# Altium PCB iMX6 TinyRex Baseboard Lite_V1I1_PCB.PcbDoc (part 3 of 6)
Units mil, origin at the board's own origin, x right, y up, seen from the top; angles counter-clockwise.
Board outline 3149.61 x 3543.31 mil, 6 copper layers (L1, L2, L3, L4 (PWR), L5, L6), stack 60.634 mil thick; 385 components, 309 nets, 1566 pads, 914 vias.
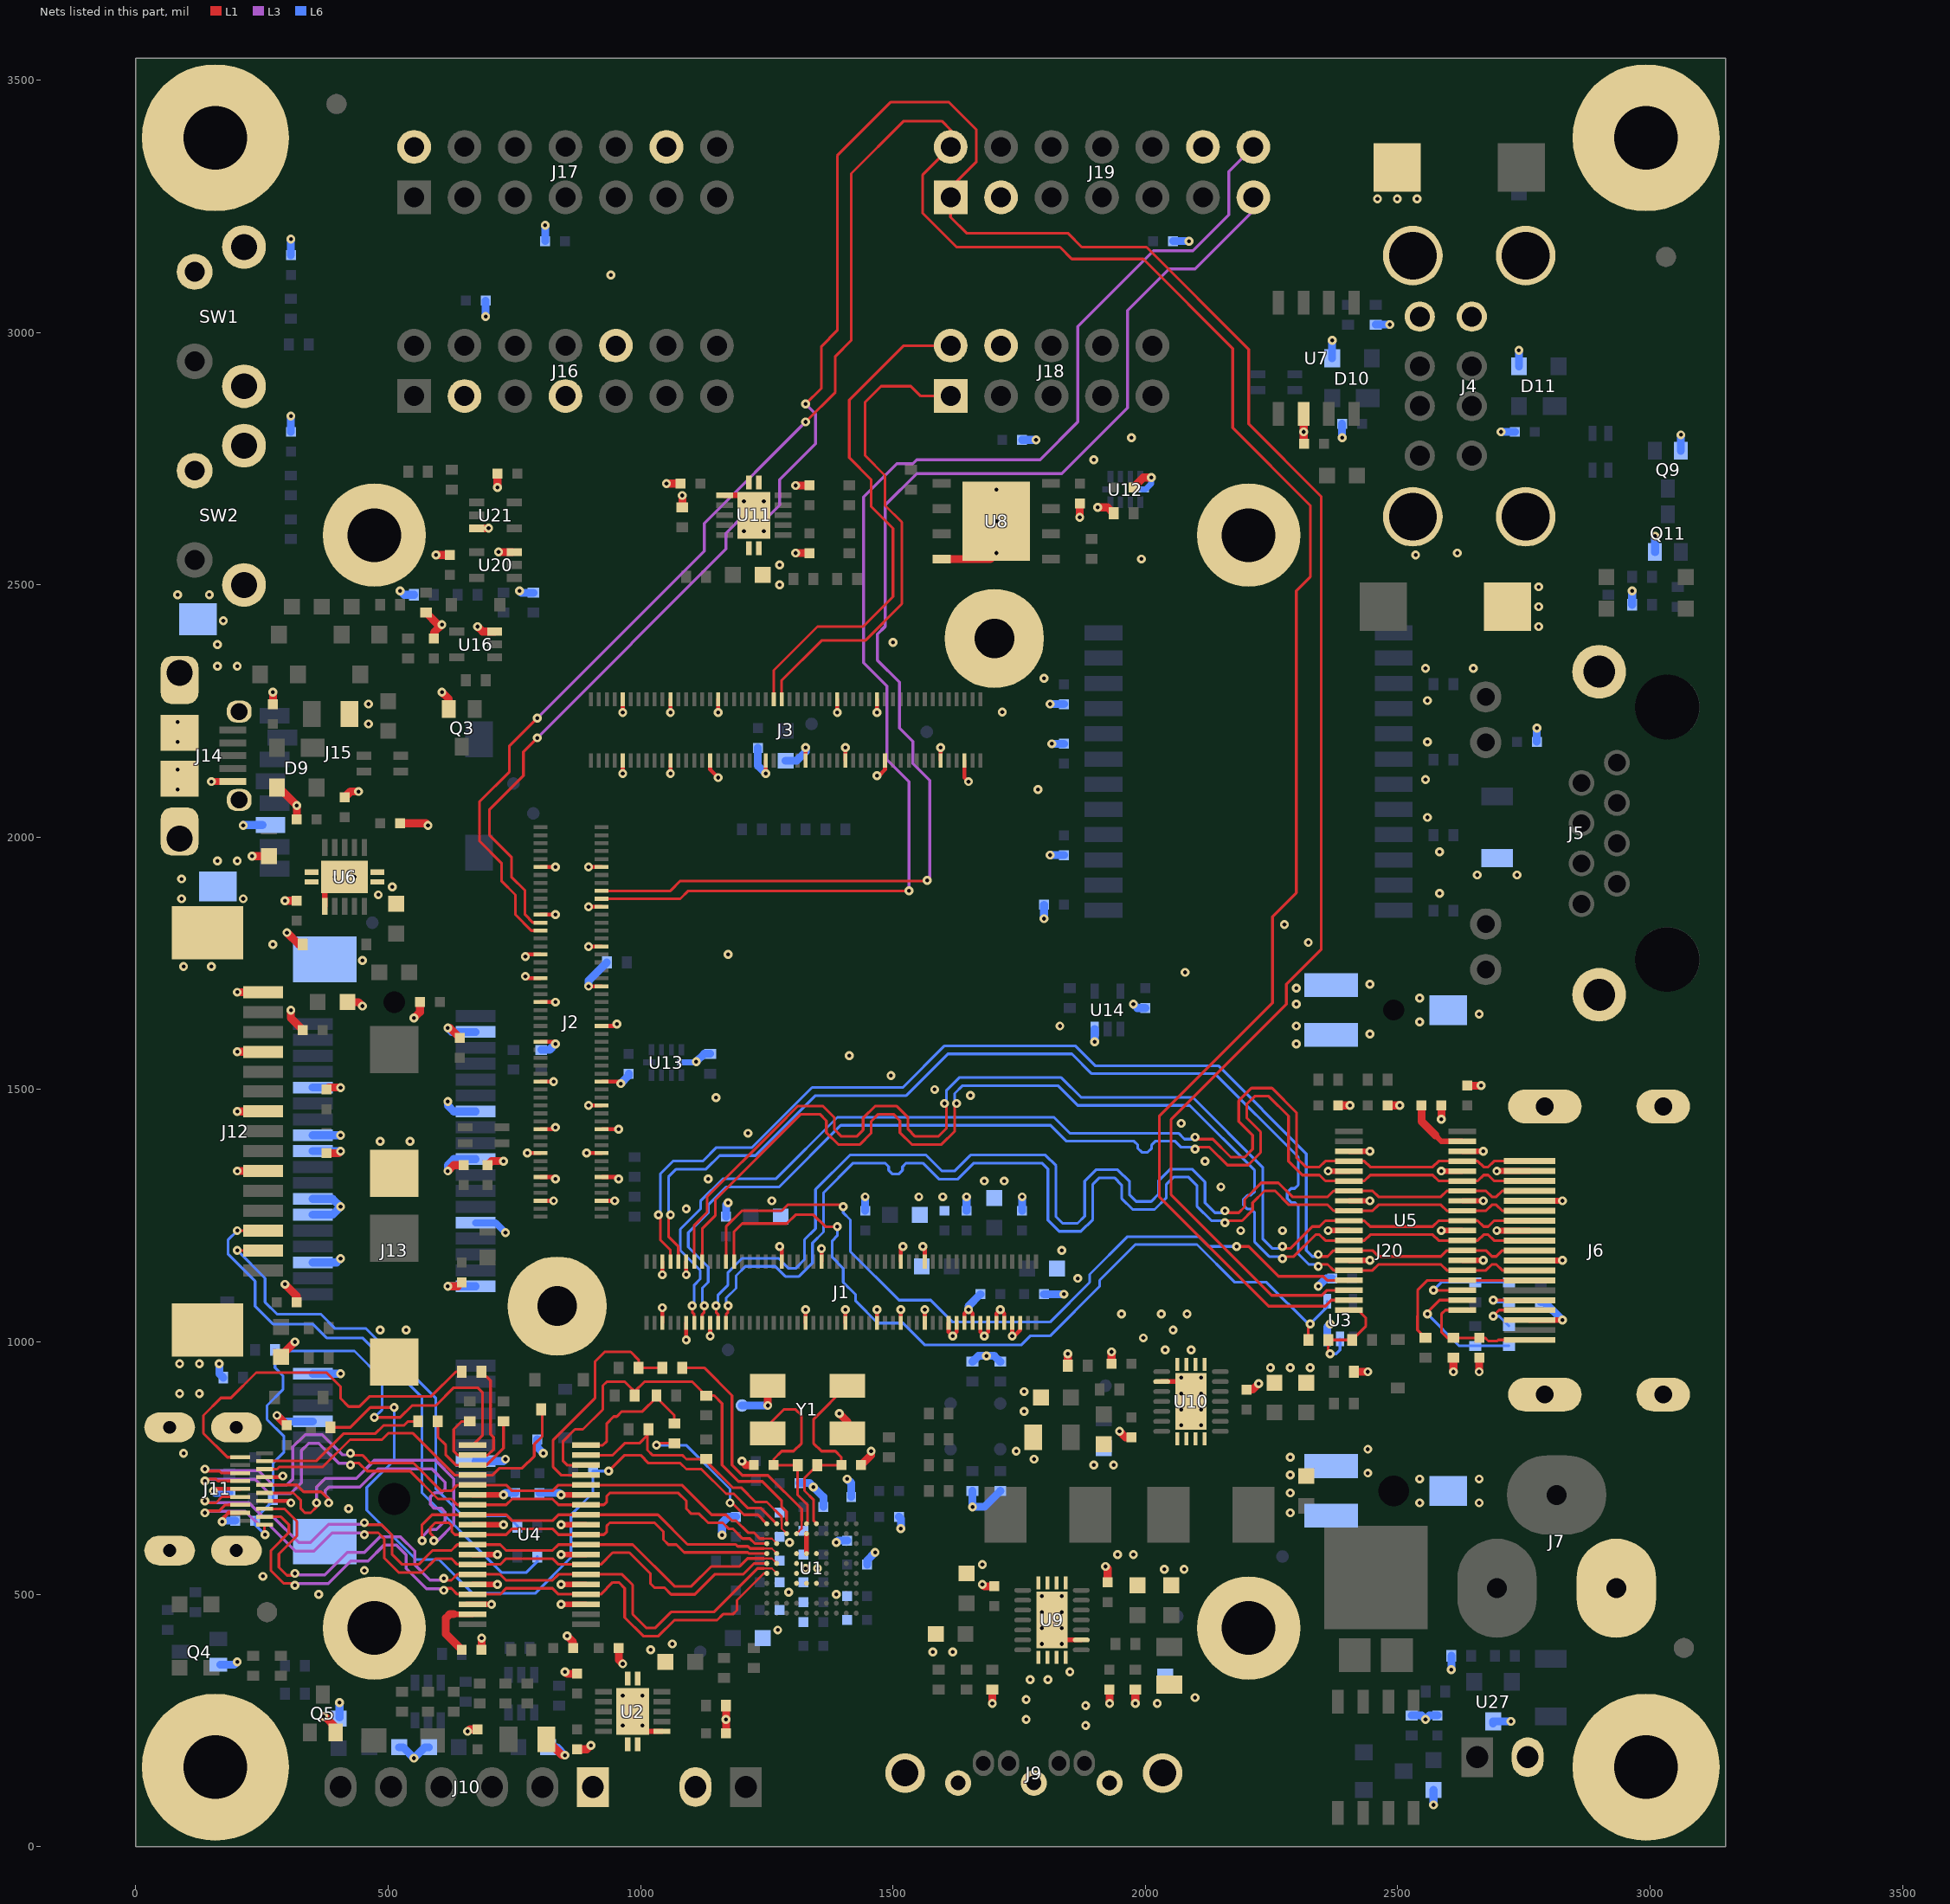
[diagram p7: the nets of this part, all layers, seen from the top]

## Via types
v1: diameter 17.72, hole 7.87, L1 to L6, 471 vias
v2: diameter 17.72, hole 7.87, L1 to L6, tented both sides, 442 vias
v3: diameter 17.72, hole 7.87, L1 to L6, tented top, 1 vias

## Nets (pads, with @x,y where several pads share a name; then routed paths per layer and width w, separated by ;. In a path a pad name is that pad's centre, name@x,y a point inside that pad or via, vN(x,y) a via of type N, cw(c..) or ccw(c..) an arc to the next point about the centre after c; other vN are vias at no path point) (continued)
GND: C1.2 C2.2 C3.2 C4.2 C5.2 C6.2 C7.2 C8.2 C9.1 C10.2 C11.2 C12.2 C13.2 C14.2 C15.2 C16.2 C17.2 C18.2 C19.2 C20.2 C21.2 C22.2 C23.2 C24.2 C25.2 C26.2 C27.1 C28.1 C29.2 C30.2 C31.2 C32.2 C33.2 C34.2 C35.2 C36.2 C37.2 C38.2 C39.2 C40.2 C41.1 C42.1 C43.1 C44.1 C45.2 C46.2 C47.2 C48.2 C49.2 C50.2 C51.2 C52.1 C53.1 C54.1 C55.1 C56.2 C57.2 C58.2 C59.2 C60.2 C61.2 C62.2 C63.2 C64.2 C65.2 C66.2 C67.2 C68.2 C69.2 C70.2 C71.2 C72.2 C73.2 C74.2 C75.1 C76.1 C77.2 C78.2 C79.2 C89.2 C90.2 C91.2 C92.2 C106.2 C108.2 C114.1 C115.2 C116.1 C117.1 C118.1 C119.2 C156.2 C158.2 C159.2 C160.2 C161.2 C165.2 C171.2 C176.2 C177.1 C183.2 C184.2 C185.2 C187.1 C188.1 C190.1 C198.2 C200.2 C203.2 C230.1 C231.2 C232.2 C257.2 C258.2 C259.2 C260.2 C261.2 C262.2 C263.2 C264.2 C265.2 C266.2 C267.2 C268.2 C381.2 D4.2 D8.2 D9.3 D10.3 D11.3 D12.2 D13.2 D19.2 J1.5 J1.7 J1.9 J1.11 J1.13 J1.15 J1.17 J1.19 J1.21 J1.23 J1.29 J1.30 J1.35 J1.36 J1.41 J1.49 J1.56 J1.59 J1.66 J1.83 J1.89 J1.90 J1.95 J1.96 J2.11 J2.12 J2.21 J2.24 J2.31 J2.34 J2.40 J2.41 J2.46 J2.51 J2.56 J2.65 J2.66 J2.71 J2.77 J2.78 J2.83 J2.84 J2.89 J2.90 J2.95 J2.96 J3.5 J3.11 J3.25 J3.28 J3.35 J3.38 J3.45 J3.55 J3.68 J3.69 J3.79 J3.80 J3.91 J3.92 J4.4 J4.8 J4.9 J4.10 J4.11 J4.12 J5.13 J5.14 J6.2 J6.5 J6.8 J6.11 J6.17 J6.MTG1 J6.MTG2 J6.MTG3 J6.MTG4 J7.2 J8.2 J9.1 J9.4 J9.7 J9.8 J9.9 J10.1 J11.4 J11.7 J11.10 J11.13 J11.MTG1 J11.MTG2 J11.MTG3 J11.MTG4 J12.1 J12.4 J12.7 J12.10 J12.16 J12.17 J13.4 J13.9 J13.15 J13.18 J13.21 J13.26 J13.27 J13.29 J13.34 J13.35 J13.37 J13.40 J13.43 J13.50 J13.53 J13.54 J14.5 J14.6 J14.7 J14.8 J14.9 J14.10 J14.11 J15.6 J15.11 J15.12 J16.3 J16.7 J16.10 J17.2 J17.12 J18.4 J19.3 J19.12 J20.1 J20.2 J20.3 J20.4 J20.5 J20.6 JP1.2 MH1.1 MH2.1 MH3.1 MH4.1 MH5.1 MH6.1 MH9.1 MH10.1 MH11.1 MH12.1 Q3.2 Q4.2 Q5.2 Q9.2 Q11.2 R1.1 R2.1 R3.1 R4.1 R14.2 R20.1 R23.1 R25.1 R29.1 R38.1 R44.1 R45.1 R47.1 R52.1 R53.1 R64.1 R67.1 R83.1 R139.1 R162.2 R213.1 R217.1 R226.1 R247.1 R296.1 R301.1 SW1.1 SW1.3 SW1.4 SW2.1 SW2.3 SW2.4 TP10.1 U1.B5 U1.D4 U1.D5 U1.D6 U1.E4 U1.F4 U1.G4 U1.G5 U1.G6 U2.6 U2.11 U2.12 U2.13 U2.14 U2.15 U3.3 U4.3 U4.5 U4.8 U4.11 U4.14 U4.25 U4.28 U4.31 U4.34 U4.36 U5.3 U5.5 U5.8 U5.11 U5.14 U5.25 U5.28 U5.31 U5.34 U5.36 U6.6 U6.11 U6.12 U6.13 U6.14 U6.15 U7.6 U8.4 U8.9 U9.2 U9.15 U9.16 U9.17 U9.18 U9.19 U9.20 U9.21 U9.22 U9.23 U10.2 U10.15 U10.16 U10.17 U10.18 U10.19 U10.20 U10.21 U10.22 U10.23 U11.6 U11.11 U11.12 U11.13 U11.14 U11.15 U12.5 U13.5 U14.3 U16.3 U20.3 U21.3 U27.3 Y1.2 Y1.4 | length 9107.6
  L1 w7.87: v1(153.54,704.72) 157.48,708.66 J11.10@206.69,708.66 ; v1(171.26,643.7) 171.26,649.2 183.47,661.42 J11.4@206.69,661.42 ; J11.7@254.92,685.04 303.15,685.04 v1(307.09,681.1) ; J11.13@254.92,732.28 289.37,732.28 v1(291.34,734.25) ; v2(771.65,1724.41) 775.59,1720.47 J2.40@801.57,1720.47 ; v2(771.65,1763.78) 775.59,1767.72 J2.34@801.57,1767.72 ; v2(775.59,1374.02) J2.84@801.57,1374.02 ; J2.96@801.57,1279.53 v2(827.56,1279.53) ; J2.90@801.57,1326.77 827.56,1326.77 v2(831.5,1322.84) ; J2.78@801.57,1421.26 827.56,1421.26 v2(831.5,1425.2) ; J2.66@801.57,1515.75 v2(827.56,1515.75) ; J2.56@801.57,1594.49 827.56,1594.49 v2(831.5,1590.55) ; J2.46@801.57,1673.23 v2(831.5,1673.23) ; J2.24@801.57,1846.46 v2(831.5,1846.46) ; J2.12@801.57,1940.94 v2(831.5,1940.94) ; v2(892.91,1374.02) J2.83@922.83,1374.02 ; v2(896.85,1468.5) J2.71@922.83,1468.5 ; v2(896.85,1704.72) J2.41@922.83,1704.72 ; v2(896.85,1783.46) J2.31@922.83,1783.46 ; v2(896.85,1862.2) J2.21@922.83,1862.2 ; v2(896.85,1940.94) J2.11@922.83,1940.94 ; J2.95@922.83,1279.53 v2(948.82,1279.53) ; J2.89@922.83,1326.77 952.76,1326.77 v2(956.69,1322.84) ; J2.77@922.83,1421.26 v2(956.69,1421.26) ; J2.65@922.83,1515.75 956.69,1515.75 v2(960.63,1511.81) ; J2.51@922.83,1625.98 948.82,1625.98 v2(952.76,1629.92) ; v2(964.57,2125.98) J3.91@964.57,2151.97 ; v2(964.57,2247.24) J3.92@964.57,2273.23 ; J1.95@1043.31,1037.8 v2(1043.31,1067.72) ; v2(1043.31,1133.07) J1.96@1043.31,1159.06 ; v2(1059.06,2125.98) J3.79@1059.06,2151.97 ; v2(1059.06,2247.24) J3.80@1059.06,2273.23 ; v2(1090.55,1003.94) J1.89@1090.55,1037.8 ; v2(1090.55,1133.07) J1.90@1090.55,1159.06 ; v2(1137.8,1011.81) J1.83@1137.8,1037.8 ; J3.69@1137.8,2151.97 1137.8,2133.86 v2(1153.54,2118.11) ; v2(1153.54,2247.24) J3.68@1153.54,2273.23 ; v2(1248.03,2125.98) J3.55@1248.03,2151.97 ; v2(1275.59,1188.98) 1279.53,1185.04 J1.66@1279.53,1159.06 ; J1.59@1326.77,1037.8 v2(1326.77,1063.78) ; J3.45@1326.77,2151.97 v2(1326.77,2177.95) ; J1.56@1358.27,1159.06 v2(1358.27,1185.04) ; v2(1389.76,2247.24) J3.38@1389.76,2273.23 ; J1.49@1405.51,1037.8 v2(1405.51,1063.78) ; J3.35@1405.51,2151.97 v2(1405.51,2177.95) ; J1.41@1468.5,1037.8 v2(1468.5,1063.78) ; v2(1468.5,2122.05) 1472.44,2122.05 1484.25,2133.86 J3.25@1484.25,2151.97 ; v2(1468.5,2247.24) J3.28@1468.5,2273.23 ; J1.35@1515.75,1037.8 v2(1515.75,1063.78) ; J1.36@1515.75,1159.06 v2@1515.75,1185.04 ; v2(1559.06,1188.98) 1562.99,1185.04 J1.30@1562.99,1159.06 ; J1.29@1562.99,1037.8 v2(1562.99,1063.78) ; J3.11@1594.49,2151.97 v2(1594.49,2177.95) ; J1.23@1610.24,1037.8 1610.24,1019.69 v2(1618.11,1011.81) 1625.98,1019.68 J1.21@1625.98,1037.8 ; J1.19@1641.73,1037.8 1641.73,1055.91 v2(1649.61,1063.78) 1657.48,1055.91 J1.17@1657.48,1037.8 ; J3.5@1641.73,2151.97 1641.73,2118.11 v2(1649.61,2110.24) ; J1.15@1673.23,1037.8 1673.23,1019.69 v2(1681.1,1011.81) 1688.98,1019.68 J1.13@1688.98,1037.8 ; J1.11@1704.72,1037.8 1704.72,1055.91 v2(1712.6,1063.78) 1720.47,1055.91 J1.9@1720.47,1037.8 ; J1.7@1736.22,1037.8 v2(1736.22,1011.81) 1740.16,1011.81 1751.97,1023.62 J1.5@1751.97,1037.8
  L1 w9.45: v1(1834.65,401.57) 1842.52,409.45 U9.2@1873.03,409.45 ; U10.2@2031.5,921.26 U10.15@2070.87,921.26
  L1 w9.84: U1.D5@1328.74,580.71 U1.B5@1328.74,620.08
  L1 w11.02: U6.6@374.02,1863.19 U6.11@374.02,1891.93 ; U4.36@655.51,480.32 v1(704.72,480.32) ; U4.34@667.32,519.69 v1(716.54,519.69) ; U4.31@667.32,578.74 v1(716.54,578.74) ; U4.28@667.32,637.8 v1(728.35,637.8) ; U4.25@667.32,696.85 v1(728.35,696.85) ; v1(842.52,480.32) U4.3@891.73,480.32 ; v1(842.52,519.69) U4.5@891.73,519.69 ; v1(842.52,578.74) U4.8@891.73,578.74 ; v1(842.52,637.8) U4.11@891.73,637.8 ; v1(842.52,696.85) U4.14@891.73,696.85 ; U2.11@1013.58,228.35 U2.6@1042.32,228.35 ; U11.6@1166.34,2677.17 U11.11@1195.08,2677.17 ; v2(2362.21,1220.47) U5.11@2403.54,1220.47 ; v2(2362.21,1338.58) U5.5@2403.54,1338.58 ; U5.14@2403.54,1161.42 v2(2444.88,1161.42) ; U5.8@2403.54,1279.53 v2(2444.88,1279.53) ; U5.3@2403.54,1377.95 v2(2444.88,1377.95) ; v2(2586.61,1220.47) U5.28@2627.95,1220.47 ; v2(2586.61,1338.58) U5.34@2627.95,1338.58 ; U5.25@2627.95,1161.42 v2(2669.29,1161.42) ; U5.31@2627.95,1279.53 v2(2669.29,1279.53) ; U5.36@2627.95,1377.95 v2(2669.29,1377.95)
  L1 w11.81: v2(2696.46,1220.47) J6.8@2761.42,1220.47 ; v2(2696.46,1338.58) J6.2@2761.42,1338.58 ; J6.17@2761.42,1043.31 v2(2826.38,1043.31) ; J6.11@2761.42,1161.42 v2(2826.38,1161.42) ; J6.5@2761.42,1279.53 v2(2826.38,1279.53)
  L1 w13.78: v1(149.61,2110.24) J14.5@191.93,2110.24
  L1 w15.75: v1(200.79,1338.58) J12.10@251.97,1338.58 ; v1(200.79,1456.69) J12.7@251.97,1456.69 ; v1(200.79,1574.8) J12.4@251.97,1574.8 ; v1(200.79,1692.91) J12.1@251.97,1692.91 ; v1(230.31,1962.6) D19.2@263.78,1962.6 ; C26.2@271.65,2263.78 v1(271.65,2287.4) ; v1(279.53,854.33) C74.2@299.21,834.65 ; C31.2@279.53,974.41 289.37,974.41 v1(314.96,1000) ; D9.3@279.53,2098.43 283.46,2098.43 v1(318.9,2062.99) C158.2@318.9,2035.43 ; v1(295.28,1114.17) 318.9,1090.55 C32.2@318.9,1078.74 ; v1(295.28,1874.02) C21.2@318.9,1874.02 ; v1(299.21,1811.02) 322.83,1787.4 R20.1@330.71,1787.4 ; v1(307.09,1657.48) 307.09,1641.73 C69.2@330.71,1618.11 ; v1(372.05,257.87) 374.02,257.87 395.67,236.22 Q5.2@395.67,226.38 ; C263.2@377.95,1374.02 401.57,1374.02 v1(405.51,1377.95) ; C268.2@377.95,1500 381.89,1503.94 v1(405.51,1503.94) ; C19.2@413.39,2078.74 425.2,2090.55 v1(440.94,2090.55) ; C60.2@419.29,1673.23 440.95,1673.23 v1(448.82,1665.35) ; C18.2@523.62,2027.56 574.8,2027.56 v1(578.74,2023.62) ; v1(551.18,1641.73) 562.99,1653.54 C267.2@562.99,1673.23 ; R45.1@574.8,2444.88 598.43,2421.26 v1(606.3,2421.26) 590.55,2405.51 C230.1@590.55,2393.7 ; v1(594.49,2559.06) C171.2@622.05,2559.06 ; v1(606.3,2287.4) 620.08,2273.62 Q3.2@620.08,2253.94 ; v1(618.11,1110.24) 637.8,1110.24 C266.2@645.67,1118.11 ; v1(618.11,1338.58) 629.92,1350.39 C260.2@649.61,1350.39 ; v1(618.11,1622.05) 622.05,1622.05 C261.2@641.73,1602.36 ; v1(657.48,228.35) 661.42,232.28 C77.2@673.23,232.28 ; U21.3@671.26,2612.2 v1(698.82,2612.2) ; v1(677.17,2417.32) 687.01,2407.48 U16.3@710.63,2407.48 ; C73.2@685.04,389.76 v1(685.04,413.39) ; C262.2@696.85,1350.39 704.72,1358.27 v1(728.35,1358.27) ; v1(716.54,2692.91) C176.2@716.54,2720.47 ; v1(718.5,2564.96) U20.3@746.06,2564.96 ; C78.2@812.99,212.6 844.49,181.1 v1(850.39,181.1) ; v1(850.39,346.46) 854.33,342.52 C56.2@874.02,342.52 ; v1(854.33,417.32) 866.14,405.51 C72.2@866.14,393.7 ; C57.2@874.02,192.91 893.7,192.91 v1(901.57,200.79) ; C71.2@956.69,393.7 956.69,370.08 v1(964.57,362.2) ; v2(1051.18,2700.79) C92.2@1078.74,2700.79 ; R226.1@1082.68,2653.54 v2(1082.68,2677.17) ; C59.2@1169.29,224.41 v1(1169.29,251.97) R83.1@1169.29,279.53 ; v1(1200.79,763.78) 1208.66,755.91 C48.2@1224.41,755.91 ; v1(1251.97,874.02) Y1.4@1251.97,913.39 ; v2(1307.09,2562.99) C89.2@1334.65,2562.99 ; v2(1307.09,2696.85) C90.2@1334.65,2696.85 ; v1(1393.7,858.27) 1409.45,842.52 Y1.2@1409.45,818.9 ; C49.2@1437.01,755.91 1456.69,775.59 v1(1456.69,783.46) ; U8.4@1596.46,2550.98 1692.72,2550.98 v1(1704.72,2562.99) ; v1(1677.17,519.69) 1681.1,515.75 C39.2@1700.79,515.75 ; v1(1696.85,283.46) R25.1@1696.85,311.02 ; R217.1@1846.46,952.76 v2(1846.46,976.38) ; v1(1870.08,2633.86) C203.2@1870.08,2661.42 ; v2(1905.51,2653.54) 1925.2,2653.54 R23.1@1937.01,2641.73 ; v1(1921.26,555.12) 1925.2,551.18 C40.2@1925.2,523.62 ; v1(1929.13,283.46) C64.2@1929.13,311.02 ; C33.2@1933.07,956.69 v2(1933.07,980.31) ; v2(1948.82,822.83) 1960.63,811.02 C68.2@1972.44,811.02 ; C9.1@1976.38,2692.91 1996.06,2712.6 v2(2011.81,2712.6) ; v1(1980.32,283.46) R213.1@1980.32,311.02 ; C67.2@2200.79,905.51 2212.6,905.51 v2(2224.41,917.32) ; C165.2@2313.58,2779.53 U7.6@2313.58,2838.58 ; C23.2@2381.89,1468.5 v2(2405.51,1468.5) ; R29.1@2413.39,940.94 v2(2440.94,940.94) ; C22.2@2480.31,1468.5 v2(2503.94,1468.5) ; v2(2586.61,1440.94) C24.2@2586.61,1468.5 ; v2(2610.24,940.94) R47.1@2610.24,968.5 ; C25.2@2637.8,1507.87 v2(2665.35,1507.87) ; v2(2661.42,940.94) C108.2@2661.42,968.5
  L6 w11.81: U13.5@1085.04,1553.67 1108.79,1553.67 v2(1110.24,1555.12) ; U12.5@1994.49,2688.98 2000.39,2688.98 2011.81,2700.4 v2(2011.81,2712.6)
  L6 w13.78: J13.26@673.23,1236.22 712.6,1236.22 v1(732.28,1216.54)
  L6 w15.75: v1(153.54,704.72) 157.48,700.79 R162.2@185.04,700.79 ; v1(165.35,956.69) 165.35,937.01 R38.1@173.23,929.13 ; Q4.2@167.32,360.24 194.88,360.24 v1(200.79,366.14) ; v1(171.26,643.7) 173.23,645.67 C8.2@196.85,645.67 ; v2@212.6,2024.21 J15.6@250.98,2024.21 ; v1(279.53,854.33) 291.34,842.52 J13.9@350.39,842.52 ; C200.2@307.09,2803.15 v1(307.09,2834.65) ; C198.2@307.09,3153.54 v1(307.09,3185.04) ; J13.15@350.39,937.01 v1(405.51,937.01) ; J13.21@350.39,1157.48 397.64,1157.48 v1(405.51,1165.35) ; J13.27@350.39,1251.97 389.76,1251.97 v1(405.51,1267.72) 389.76,1283.47 J13.29@350.39,1283.47 ; J13.35@350.39,1377.95 v1(405.51,1377.95) ; J13.37@350.39,1409.45 v1(405.51,1409.45) ; J13.43@350.39,1503.94 v1(405.51,1503.94) ; D12.2@403.54,255.91 v1(403.54,285.43) ; D8.2@521.65,196.85 529.53,196.85 v1(551.18,175.2) 572.83,196.85 D4.2@580.71,196.85 ; v1(523.62,2488.19) 531.5,2480.31 R64.1@551.18,2480.31 ; v1(618.11,1110.24) J13.18@673.23,1110.24 ; v1(618.11,1338.58) 618.11,1350.39 629.92,1362.21 J13.34@673.23,1362.21 ; v1(618.11,1476.38) 618.11,1468.5 629.92,1456.69 J13.40@673.23,1456.69 ; v1(618.11,1622.05) 625.98,1614.17 J13.50@673.23,1614.17 ; J13.4@673.23,763.78 728.35,763.78 v1(732.28,767.72) ; v1(692.91,3031.5) C36.2@692.91,3062.99 ; v1(728.35,696.85) 732.28,700.79 C265.2@751.97,700.79 ; v1(759.84,2488.19) 763.78,2484.25 R67.1@787.4,2484.25 ; C259.2@795.28,807.09 795.28,791.34 v1(807.09,779.53) ; C264.2@799.21,700.79 838.58,700.79 v1(842.52,696.85) ; R247.1@803.15,1578.74 819.68,1578.74 v2(831.5,1590.55) ; C28.1@811.02,3181.1 v1(811.02,3212.6) ; D13.2@816.93,196.85 834.65,196.85 v1(850.39,181.1) ; v2(896.85,1704.72) 896.85,1715.75 R139.1@933.07,1751.97 ; v2(896.85,1783.46) v2@897.64,1783.46 ; v2(960.63,1511.81) 976.38,1527.56 C75.1@976.38,1531.5 ; v2(1110.24,1555.12) 1125.98,1570.87 R44.1@1137.8,1570.87 ; v1(1161.42,617.13) 1161.42,641.73 1173.23,653.54 C188.1@1188.98,653.54 ; C15.2@1169.29,1248.03 1169.29,1271.65 v2(1173.23,1275.59) ; TP10.1@1200.79,874.02 v1(1251.97,874.02) ; C14.2@1232.28,2177.17 1232.28,2141.73 v2(1248.03,2125.98) ; C232.2@1287.4,2151.57 1309.06,2151.57 1326.77,2169.29 v2(1326.77,2177.95) ; C190.1@1314.96,720.47 1334.65,720.47 v1(1342.52,712.6) 1362.2,692.91 C51.2@1362.2,673.23 ; v1(1387.8,602.36) 1391.73,606.3 C45.2@1409.45,606.3 ; v1(1409.45,728.35) 1417.32,720.47 C44.1@1417.32,692.91 ; C13.2@1444.88,1259.84 v2(1444.88,1287.4) ; C46.2@1448.82,559.06 1448.82,566.93 v1(1464.57,582.68) ; C41.1@1511.81,653.54 1515.75,649.61 v1(1515.75,629.92) ; C7.2@1645.67,1259.84 v2(1645.67,1287.4) ; v2(1649.61,1063.78) 1649.61,1070.87 C6.2@1673.23,1094.49 ; R3.1@1657.48,704.72 v1(1657.48,673.23) 1681.1,673.23 R4.1@1712.6,704.72 ; R1.1@1657.48,960.63 1669.29,972.44 v1(1685.04,972.44) 1700.79,972.44 R2.1@1712.6,960.63 ; C4.2@1755.91,1259.84 v2(1755.91,1287.4) ; C34.2@1755.91,2787.4 v2(1783.46,2787.4) ; C5.2@1799.21,1094.49 v2@1838.21,1094.49 ; v2(1799.21,1838.58) C114.1@1799.21,1866.14 ; v2(1811.02,1964.57) C116.1@1838.58,1964.57 ; v2(1811.02,2263.78) C118.1@1838.58,2263.78 ; v2(1814.96,2185.04) C117.1@1838.58,2185.04 ; v2(1899.61,1594.49) U14.3@1899.61,1620.08 ; v2(1976.38,1669.29) 1984.25,1661.42 C76.1@2000,1661.42 ; C27.1@2055.12,3181.1 v1(2086.61,3181.1) ; v2(2342.52,1110.24) 2358.27,1125.98 C35.2@2370.08,1125.98 ; U3.3@2360.24,1005.91 2360.24,1029.53 v2(2366.14,1035.43) ; D10.3@2370.08,2948.82 v1(2370.08,2984.25) ; v2(2389.76,2791.34) C160.2@2389.76,2818.9 ; R52.1@2456.69,3015.75 v1(2484.25,3015.75) ; R301.1@2527.56,259.84 2547.24,259.84 v1(2555.12,251.97) 2562.99,259.84 C79.2@2578.74,259.84 ; v1(2570.87,82.68) C10.2@2570.87,112.2 ; v1(2606.3,350.39) R296.1@2606.3,377.95 ; U27.3@2688.98,248.03 v1(2724.41,248.03) ; v2(2704.72,2803.15) C161.2@2732.28,2803.15 ; D11.3@2740.16,2933.07 v2(2740.16,2964.57) ; C115.2@2775.59,2188.98 v2(2775.59,2216.54) ; R14.2@2783.46,1078.74 2790.95,1078.74 v2(2826.38,1043.31) ; R53.1@2964.57,2460.63 v1(2964.57,2488.19) ; Q11.2@3009.84,2564.96 v1(3009.84,2596.46) ; Q9.2@3061.02,2765.75 v1(3061.02,2797.24)
  other v1: 964.57,240.16 1003.94,240.16 1881.89,240.16 1763.78,251.97 1881.89,279.53 2023.62,283.46 1763.78,291.34 2098.43,295.28 964.57,299.21 1003.94,299.21 1771.65,330.71 1807.09,330.71 1850.39,346.46 1578.74,385.83 1618.11,385.83 1019.69,389.76 1062.99,401.57 1795.28,401.57 1271.65,429.13 1795.28,433.07 1834.65,433.07 1795.28,464.57 1834.65,464.57 1795.28,496.06 1834.65,496.06 362.2,500 1387.8,500 1293.31,503.94 251.97,535.43 452.76,547.24 2037.4,549.21 2076.77,549.21 1326.77,551.18 1350.39,551.18 1677.17,559.06 1944.88,578.74 1976.38,578.74 1295.28,602.36 2287.4,661.42 421.26,669.29 2287.4,700.79 94.49,779.53 2070.87,834.65 2110.24,834.65 2070.87,866.14 2110.24,866.14 86.61,897.64 125.98,897.64 2070.87,897.64 2110.24,897.64 2070.87,929.13 2110.24,929.13 86.61,956.69 125.98,956.69 2039.37,984.25 2090.55,984.25 1996.06,1007.87 484.25,1023.62 535.43,1023.62 2055.12,1023.62 1952.76,1055.12 2031.5,1055.12 2082.68,1055.12 484.25,1397.64 543.31,1397.64 94.49,1744.09 149.61,1744.09 448.82,1755.91 271.65,1787.4 90.55,1877.95 212.6,1877.95 480.32,1885.83 507.87,1901.57 90.55,1917.32 393.7,1921.26 433.07,1921.26 161.42,1952.76 200.79,1952.76 82.68,2094.49 82.68,2133.86 82.68,2188.98 460.63,2224.41 82.68,2228.35 460.63,2263.78 161.42,2338.58 200.79,2338.58 161.42,2381.89 173.23,2429.13 82.68,2480.31 145.67,2480.31 1992.13,2551.18 1204.72,2606.3 1244.09,2606.3 1704.72,2625.98 1204.72,2665.35 1244.09,2665.35 1704.72,2688.98
  other v2: 2543.31,681.1 2661.42,681.1 2543.31,728.35 2661.42,728.35 2287.4,736.22 2440.94,740.16 1897.64,755.91 1937.01,755.91 1779.53,767.72 2287.4,771.65 1744.09,783.46 2440.94,787.4 1759.84,862.2 1759.84,901.57 2248.03,948.82 2287.4,948.82 2326.77,948.82 1838.58,1094.49 1866.14,1125.98 1834.65,1181.1 1519.69,1188.98 2188.98,1220.47 2271.65,1220.47 1090.55,1263.78 1259.84,1279.53 1551.18,1287.4 1598.43,1287.4 2149.61,1307.09 1681.1,1318.9 1720.47,1318.9 1133.86,1322.83 2118.11,1358.27 1212.6,1413.39 2070.87,1433.07 1149.61,1484.25 1653.54,1488.19 1582.68,1500 1496.06,1527.56 1413.39,1566.93 2299.21,1590.55 2444.88,1610.24 1830.71,1625.98 2299.21,1625.98 2543.31,1633.86 2661.42,1649.61 2299.21,1669.29 2543.31,1681.1 2299.21,1700.79 2444.88,1708.66 2078.74,1732.28 1173.23,1767.72 2322.83,1791.34 2275.59,1826.77 2582.68,1888.98 2657.48,1925.2 2736.22,1925.2 2582.68,1970.87 212.6,2023.62 2558.96,2039.17 1787.4,2094.49 2555.12,2114.17 2558.96,2188.78 1716.54,2248.03 2558.96,2270.67 1799.21,2314.96 2555.12,2334.65 2649.61,2334.65 1500,2385.83 2779.53,2417.32 2779.53,2456.69 2779.53,2496.06 1275.59,2500 1275.59,2539.37 2535.43,2559.06 2618.11,2562.99 1897.64,2748.03 1972.44,2791.34 2313.58,2803.15 940.94,3114.17 2459.84,3264.57 2499.21,3264.57 2538.58,3264.57
GPIO_OR_PWM_1: J2.17 J19.13 | length 2558.5
  L1 w5.4: J2.17@922.83,1893.7 1059.05,1893.7 1078.74,1913.39 v2@1567.72,1913.39
  L3 w5.9: v2(1567.72,1914.17) 1572.83,1919.29 1572.83,2112.2 1539.37,2145.67 1539.37,2189.81 1512.6,2216.58 1512.6,2307.13 1469.29,2350.44 1469.29,2402.36 1484.25,2417.32 1484.25,2657.48 1547.24,2720.47 1834.65,2720.47 1964.57,2850.39 1964.57,3043.31 2047.24,3125.98 2098.43,3125.98 2214.17,3241.73 J19.13@2214.17,3267.72
GPIO_OR_PWM_2: J2.19 J19.14 | length 2653.4
  L1 w5.4: J2.19@922.83,1877.95 1078.74,1877.95 1094.49,1893.7 v2(1531.5,1893.7)
  L3 w5.9: v2(1531.5,1893.7) 1531.5,2110.24 1488.19,2153.54 1488.19,2299.21 1441.73,2345.67 1441.73,2674.02 1507.87,2740.16 1539.37,2740.16 1547.24,2748.03 1791.34,2748.03 1866.14,2822.83 1866.14,3011.81 2016.54,3162.2 2094.44,3162.2 2165.35,3233.12 2165.35,3318.9 J19.14@2214.17,3367.72
GPIO_OR_PWM_3: J3.52 J18.1 | length 959
  L1 w5.4: J3.52@1279.53,2273.23 1279.53,2311.02 1358.27,2389.76 1444.88,2389.76 1517.72,2462.6 1517.72,2533.46 1517.52,2533.66 1517.52,2624.21 1484.25,2657.48 1484.25,2716.54 1444.88,2755.91 1444.88,2862.2 1476.38,2893.7 1535.43,2893.7 1555.12,2874.02 J18.1@1614.17,2874.02
GPIO_OR_PWM_4: J3.54 J18.2 | length 1025.1
  L1 w5.4: J3.54@1263.78,2273.23 1263.78,2330.71 1350.39,2417.32 1440.94,2417.32 1500,2476.38 1500,2611.95 1456.69,2655.25 1456.69,2708.66 1413.39,2751.97 1413.39,2866.14 1521.26,2974.02 J18.2@1614.17,2974.02
HDMI_HPA_A: R165.2 U1.A1 | length 336.1
  L1 w5.4: v1(1031.5,795.28) 1035.43,799.21 R165.2@1066.93,799.21 ; v1(1177.17,681.1) 1181.1,681.1 1204.72,657.48 1232.28,657.48 U1.A1@1250,639.76
  L6 w5.4: v1(1031.5,795.28) 1090.51,795.28 1177.17,708.62 v1(1177.17,681.1)
HDMI_IN_CEC: R105.2 U1.B4 | length 486.2
  L1 w3.94: U1.B4@1309.06,620.08 1318.9,629.92 1318.9,645.67
  L1 w5.4: R105.2@1082.68,948.82 1125.98,948.82 1181.1,893.7 1181.1,755.91 1201.38,735.63 1252.56,735.63 1319.09,669.09 1319.09,645.87 1318.9,645.67
HDMI_IN_CEC_CON: J11.15 R50.2 U4.23 | length 713.6
  L1 w5.4: J11.15@254.92,748.03 279.78,748.03 283.92,752.17 370.28,752.17 424.41,806.3 487.4,806.3 500,818.9 548.96,818.9 631.63,736.22 U4.23@667.32,736.22 706.89,736.22 720.47,749.8 765.55,749.8 789.17,773.43 789.17,797.05 805.32,813.19 805.32,863.98 R50.2@803.15,866.14
HDMI_IN_CEC_IN: R12.1 R105.1 U4.16 | length 478.7
  L1 w5.4: U4.16@891.73,736.22 842.52,736.22 826.77,751.97 826.77,805.65 909.45,888.33 909.45,960.63 929.13,980.31 980.31,980.31 996.06,964.57 R12.1@996.06,948.82 R105.1@1043.31,948.82
HDMI_IN_CLK_N: J11.14 U1.C2 U4.15 U4.24 | length 1409.2
  L1 w3.94: 1244.09,610.24 1259.84,610.24 U1.C2@1269.69,600.39
  L1 w5.4: v1(136.81,748.03) 140.67,744.18 165.35,744.18 169.29,740.24 183.97,740.24 184.05,740.16 J11.14@206.69,740.16 ; v1(425.2,779.53) 429.05,775.67 448.74,775.67 464.41,760 549.9,760 605.1,704.81 625.08,704.81 636.81,716.54 U4.24@667.32,716.54 733.72,716.54 745.45,704.81 825.42,704.81 837.15,716.54 U4.15@891.73,716.54 1081.56,716.54 1140.61,657.48 1169.15,657.48 1180.8,645.83 1188.9,645.83 1212.6,622.13 1224.33,622.13 1236.22,610.24 1244.09,610.24
  L3 w6: v1(136.81,748.03) 140.08,744.77 243.42,744.77 271.7,716.49 299.17,716.49 311.02,728.35 311.02,791.89 335.44,816.3 369.41,816.3 409.45,776.26 421.93,776.26 v1(425.2,779.53)
HDMI_IN_CLK_P: J11.12 U1.C1 U4.13 U4.26 | length 1408.8
  L1 w5.4: v1(136.81,724.41) 140.67,728.27 158.76,728.27 162.7,724.33 183.97,724.33 184.05,724.41 J11.12@206.69,724.41 ; v1(425.2,755.91) 429.05,759.76 442.15,759.76 457.81,744.09 543.31,744.09 598.51,688.9 625.08,688.9 636.81,677.17 U4.26@667.32,677.17 733.72,677.17 745.45,688.9 825.42,688.9 837.15,677.17 U4.13@891.73,677.17 927.17,677.17 933.07,683.07 933.07,694.88 938.81,700.63 1074.97,700.63 1090.55,685.04 1090.55,669.29 1100.39,659.45 1116.14,659.45 1134.02,641.57 1162.56,641.57 1174.21,629.92 1182.31,629.92 1201.99,610.24 1216.54,610.24 1226.38,600.39 U1.C1@1250,600.39
  L3 w6: v1(136.81,724.41) 140.08,727.68 236.34,727.68 264.62,699.4 306.24,699.4 328.11,721.27 328.11,784.81 342.52,799.21 362.33,799.21 402.37,759.17 421.93,759.17 v1(425.2,755.91)
HDMI_IN_D0_N: J11.11 U1.D2 U4.12 U4.27 | length 1406.2
  L1 w3.94: 1244.09,590.55 1259.84,590.55 U1.D2@1269.69,580.71
  L1 w5.4: J11.11@254.92,716.54 274.61,716.54 274.69,716.62 318.77,716.62 332.47,702.92 367.3,702.92 381.89,688.33 v1(381.89,681.1) ; v1(566.93,606.3) 566.93,637.8 586.61,657.48 U4.27@667.32,657.48 733.72,657.48 745.45,645.75 825.42,645.75 837.15,657.48 U4.12@891.73,657.48 1034.31,657.48 1092.97,598.82 1188.58,598.82 1192.52,594.88 1212.6,594.88 1216.93,590.55 1244.09,590.55
  L3 w6: v1(381.89,681.1) 381.89,689.93 375.36,696.47 375.36,705.52 382.44,712.6 444.05,712.6 479.49,748.03 586.61,748.03 612.83,721.81 612.83,708.66 605.68,701.51 591.72,701.51 583.84,693.64 583.84,677.89 591.72,670.01 605.64,670.01 612.83,662.82 612.83,645.67 595.66,628.5 581.36,628.5 566.93,614.07 v1(566.93,606.3)
HDMI_IN_D0_P: J11.9 U1.D1 U4.10 U4.29 | length 1402.2
  L1 w5.4: J11.9@254.92,700.79 274.61,700.79 274.69,700.71 312.18,700.71 326.85,686.03 326.85,669.21 334.65,661.42 346.46,661.42 358.27,673.23 v1(358.27,681.1) ; v1(590.55,606.3) 590.55,613.53 582.84,621.24 582.84,631.21 593.2,641.57 620.24,641.57 625.98,635.83 625.98,624.02 631.89,618.11 U4.29@667.32,618.11 733.72,618.11 745.45,629.84 825.42,629.84 837.15,618.11 U4.10@891.73,618.11 927.17,618.11 933.07,624.02 933.07,635.83 938.81,641.57 1027.72,641.57 1045.28,624.02 1045.28,608.27 1055.12,598.43 1070.87,598.43 1086.38,582.91 1212.37,582.91 1214.57,580.71 U1.D1@1250,580.71
  L3 w6: v1(358.27,681.1) 358.27,712.6 375.36,729.69 436.97,729.69 472.41,765.12 593.69,765.12 629.92,728.89 629.92,638.59 597.63,606.3 v1(590.55,606.3)
HDMI_IN_D1_N: J11.8 U1.E2 U4.9 U4.30 | length 1403.5
  L1 w3.94: 1244.09,570.87 1259.84,570.87 U1.E2@1269.69,561.02
  L1 w5.4: v1(136.81,685.04) 140.67,681.18 158.68,681.18 170.49,692.99 183.97,692.99 184.05,692.91 J11.8@206.69,692.91 ; v1(452.76,641.73) 456.61,637.88 486.71,637.88 507.87,616.71 507.87,578.74 527.56,559.06 560.18,559.06 587.82,586.7 625.08,586.7 636.81,598.43 U4.30@667.32,598.43 721.91,598.43 733.64,586.7 825.42,586.7 837.15,598.43 U4.9@891.73,598.43 984.25,598.43 1066.93,515.75 1100.79,515.75 1140.32,555.28 1196.33,555.28 1211.91,570.87 1244.09,570.87
  L3 w6: v1(136.81,685.04) 140.08,681.77 223.74,681.77 251.8,653.71 271.48,653.71 322.83,602.36 345.91,602.36 382.01,638.47 449.49,638.47 v1(452.76,641.73)
HDMI_IN_D1_P: J11.6 U1.E1 U4.7 U4.32 | length 1403.5
  L1 w5.4: v1(136.81,661.42) 140.67,665.27 165.27,665.27 177.08,677.08 183.97,677.08 184.05,677.17 J11.6@206.69,677.17 ; v1(452.76,618.11) 456.61,621.97 480.12,621.97 491.96,610.12 491.96,572.15 520.97,543.15 566.77,543.15 594.41,570.79 625.08,570.79 636.81,559.06 U4.32@667.32,559.06 721.91,559.06 733.64,570.79 825.42,570.79 837.15,559.06 U4.7@891.73,559.06 921.26,559.06 944.72,582.52 977.66,582.52 1019.69,540.49 1019.69,520.81 1027.56,512.93 1047.24,512.93 1060.34,499.84 1107.38,499.84 1146.91,539.37 1202.92,539.37 1224.57,561.02 U1.E1@1250,561.02
  L3 w6: v1(136.81,661.42) 140.08,664.68 216.66,664.68 244.72,636.62 264.4,636.62 315.76,585.27 352.99,585.27 389.09,621.38 449.49,621.38 v1(452.76,618.11)
HDMI_IN_D2_N: J11.5 U1.F2 U4.6 U4.33 | length 1407.5
  L1 w3.94: 1244.09,551.18 1259.84,551.18 U1.F2@1269.69,541.34
  L1 w5.4: J11.5@254.92,669.29 274.61,669.29 274.69,669.37 294.07,669.37 319.06,644.39 319.06,615.46 283.46,579.86 283.46,553.23 299.21,537.48 311.1,537.48 v1(314.96,541.34) ; v1(610.24,531.5) 614.09,527.64 625.08,527.64 636.81,539.37 U4.33@667.32,539.37 721.91,539.37 733.64,527.64 825.42,527.64 837.15,539.37 U4.6@891.73,539.37 963.44,539.37 984.41,518.4 984.41,460.47 1011.81,433.07 1028.68,433.07 1060.34,464.73 1144.98,464.73 1231.44,551.18 1244.09,551.18
  L3 w6: v1(314.96,541.34) 318.23,538.07 374.02,538.07 418.62,582.68 452.76,582.68 484.25,614.17 523.62,614.17 552.52,585.27 552.52,558.38 582.68,528.23 606.97,528.23 v1(610.24,531.5)
HDMI_IN_D2_P: J11.3 U1.F1 U4.4 U4.35 | length 1407.5
  L1 w5.4: J11.3@254.92,653.54 274.61,653.54 274.69,653.46 287.48,653.46 303.15,637.8 303.15,622.05 267.55,586.45 267.55,546.64 292.62,521.57 311.1,521.57 v1(314.96,517.72) ; v1(610.24,507.87) 614.09,511.73 625.08,511.73 636.81,500 U4.35@667.32,500 721.91,500 733.64,511.73 825.42,511.73 837.15,500 U4.4@891.73,500 921.26,500 944.72,523.46 956.85,523.46 968.5,511.81 968.5,453.88 1005.22,417.16 1035.27,417.16 1066.93,448.82 1151.57,448.82 1163.39,460.63 1183.07,460.63 1190.94,468.5 1190.94,488.19 1244.09,541.34 U1.F1@1250,541.34
  L3 w6: v1(314.96,517.72) 318.23,520.98 381.09,520.98 425.7,565.59 459.83,565.59 491.33,597.08 516.54,597.08 535.43,578.19 535.43,551.31 575.6,511.14 606.97,511.14 v1(610.24,507.87)
HDMI_IN_ESD_BYP: C73.1 U4.37 | length 132.4
  L1 w11.02: 629.92,460.63 U4.37@667.32,460.63
  L1 w15.75: 629.92,460.63 622.05,460.63 614.17,452.76 614.17,421.26 C73.1@645.67,389.76
HDMI_IN_HPD: R13.1 R165.1 U4.19 | length 269.5
  L1 w5.4: U4.19@891.73,795.28 925.2,795.28 933.07,803.15 933.07,838.58 946.65,852.17 952.76,852.17 962.8,862.2 1003.94,862.2 R13.1@1031.5,889.76 ; R13.1@1031.5,893.7 R13.1@1031.5,889.76 ; R165.1@1066.93,838.58 1066.93,854.33 R13.1@1031.5,889.76
HDMI_IN_HPD_CON: C8.1 J11.1 R39.2 R51.1 U4.20 | length 1126.6
  L1 w5.4: J11.1@254.92,637.8 254.92,619.09 v1(255.91,618.11) ; v1(472.44,850.39) 523.62,850.39 547.24,874.02 594.49,874.02 629.92,909.45 677.17,909.45 687.01,899.61 687.01,814.96 U4.20@667.32,795.28
  L6 w5.4: v1(255.91,618.11) 236.22,637.8 C8.1@236.22,645.67 236.22,649.61 271.65,685.04 R39.2@271.65,688.98 271.65,759.84 293.5,781.69 293.5,812.8 259.84,846.46 259.84,874.02 291.34,905.51 291.34,933.07 275.59,948.82 R51.1@275.59,984.25 277.76,982.09 433.01,982.09 488.19,926.91 488.19,866.14 v1(472.44,850.39)
HDMI_IN_RXA_5V: R104.2 R174.2 U1.A2 | length 1493.3
  L1 w5.4: R174.2@385.83,830.71 425.2,830.71 464.57,870.08 v1(511.81,870.08) ; v2(937.01,744.09) 968.5,775.59 1000,775.59 1015.75,759.84 1078.74,759.84 1090.55,748.03 1120.54,748.03 1169.55,699.02 1184.59,699.02 1212.93,670.67 1238.78,670.67 U1.A2@1269.69,639.76
  L6 w5.4: v1(511.81,870.08) 511.81,765.81 457.48,711.48 457.48,666.47 555.12,568.83 600.46,568.83 667.52,501.77 790.88,501.77 862.2,573.09 862.2,657.48 905.51,700.79 R104.2@905.51,744.09 v2(937.01,744.09)
HDMI_IN_SCL_CON: J11.17 R163.1 | length 332
  L1 w5.4: J11.17@259.45,764.37 357.88,764.37 412.02,818.5 474.61,818.5 490.75,834.65 531.5,834.65 539.37,842.52 R163.1@559.06,842.52
HDMI_IN_SCL_CON_R: R49.1 R163.2 U4.22 | length 262.7
  L1 w5.4: R163.2@598.43,842.52 598.43,811.02 614.17,795.28 614.17,775.59 633.86,755.91 U4.22@667.32,755.91 694.68,755.91 728.35,789.57 R49.1@728.35,842.52
HDMI_IN_SDA_CON: J11.18 R164.1 | length 745
  L1 w5.4: J11.18@206.69,771.65 181.1,771.65 133.86,818.9 133.86,854.33 168.44,888.91 188.12,888.91 238.39,939.17 377.76,939.17 405.51,911.42 405.51,888.05 421.71,871.85 442.72,871.85 462.6,891.73 584.65,891.73 633.86,940.94 R164.1@645.67,940.94
HDMI_IN_SDA_CON_R: R48.1 R164.2 U4.21 | length 331.7
  L1 w5.4: R48.1@661.42,842.52 645.67,842.52 629.92,826.77 629.92,783.46 637.8,775.59 U4.21@667.32,775.59 697.11,775.59 708.66,787.14 708.66,811.02 702.76,816.93 702.76,923.23 R164.2@685.04,940.94
HDMI_IN_XTALN: C48.1 R72.1 U1.A5 Y1.1 | length 408.1
  L1 w5.4: Y1.1@1251.97,818.9 1251.97,834.65 1283.46,866.14 1307.09,866.14 1318.9,854.33 1318.9,799.21 1303.15,783.46 1279.53,783.46 1263.78,767.72 C48.1@1263.78,755.91 R72.1@1311.02,755.91 1311.02,696.85 1330.71,677.17 1330.71,641.73 U1.A5@1328.74,639.76
HDMI_IN_XTALP: C49.1 R72.2 U1.A6 Y1.3 | length 408.1
  L1 w5.4: U1.A6@1348.43,639.76 1342.91,645.28 1342.91,686.87 1324.61,705.18 1324.61,730.12 R72.2@1350.39,755.91 C49.1@1397.64,755.91 1397.64,771.65 1385.83,783.46 1358.27,783.46 1342.52,799.21 1342.52,846.46 Y1.3@1409.45,913.39
HDMI_OUT_CEC_CON: J6.13 R21.2 U5.23 | length 339.6
  L1 w5.4: 2539.37,1051.18 2539.37,1102.36 2559.06,1122.05 ; 2553.15,1116.14 2559.06,1122.05 ; J6.13@2761.42,1122.05 U5.23@2627.95,1122.05 2559.06,1122.05
  L1 w5.91: 2539.37,1051.18 2539.37,1023.62 R21.2@2555.12,1007.87
HDMI_OUT_CEC_IN: J1.80 U5.16 | length 1579.5
  L1 w5.4: J1.80@1169.29,1159.06 1169.29,1228.35 1200.79,1259.84 1279.53,1259.84 1291.34,1271.65 1397.64,1271.65 v2(1401.57,1267.72) ; v2(2181.1,1188.98) 2204.72,1188.98 2263.78,1129.92 2352.3,1129.92 2360.18,1122.05 U5.16@2403.54,1122.05
  L6 w5.4: v2(1401.57,1267.72) 1401.57,1255.91 1415.55,1241.93 1415.55,1178.94 1511.81,1082.68 1574.8,1082.68 1618.11,1039.37 1811.02,1039.37 1889.76,1118.11 1889.76,1133.86 1964.57,1208.66 2106.3,1208.66 2125.98,1188.98 v2(2181.1,1188.98) ; v2@2183.07,1190.94 v2@2185.04,1188.98
HDMI_OUT_CLK_N: J1.92 J6.12 U5.15 U5.24 | length 2325.2
  L1 w5.4: v2(1059.06,1251.97) 1055.2,1248.11 1055.2,1208.58 1074.89,1188.89 1074.89,1175.87 1074.8,1175.79 J1.92@1074.8,1159.06 ; v2(2342.52,1149.61) 2346.38,1153.46 2361.3,1153.46 2373.03,1141.73 U5.15@2403.54,1141.73 2450.25,1141.73 2461.98,1153.46 2585.71,1153.46 2597.44,1141.73 U5.24@2627.95,1141.73 2674.66,1141.73 2686.39,1153.46 2695.55,1153.46 2707.28,1141.73 J6.12@2761.42,1141.73
  L6 w5.4: v2(1059.06,1251.97) 1055.2,1255.82 1055.2,1326.85 1070.7,1342.36 1129.76,1342.36 1156.63,1369.23 1227.5,1369.23 1346.46,1488.19 1526.44,1488.19 1608.95,1570.7 1854.49,1570.7 1893.86,1531.33 2137.96,1531.33 2302.99,1366.3 2302.99,1311.02 2295.84,1303.87 2288.95,1303.87 2281.07,1296 2281.07,1284.19 2288.95,1276.31 2295.8,1276.31 2302.99,1269.12 2302.99,1174.59 2324.12,1153.46 2338.66,1153.46 v2(2342.52,1149.61)
HDMI_OUT_CLK_P: J1.94 J6.10 U5.13 U5.26 | length 2325.4
  L1 w5.4: v2(1035.43,1251.97) 1039.29,1248.11 1039.29,1201.99 1058.98,1182.3 1058.98,1175.87 1059.06,1175.79 J1.94@1059.06,1159.06 ; v2(2342.52,1173.23) 2346.38,1169.37 2361.3,1169.37 2373.03,1181.1 U5.13@2403.54,1181.1 2450.25,1181.1 2461.98,1169.37 2585.71,1169.37 2597.44,1181.1 U5.26@2627.95,1181.1 2674.66,1181.1 2686.39,1169.37 2695.55,1169.37 2707.28,1181.1 J6.10@2761.42,1181.1
  L6 w5.4: v2(1035.43,1251.97) 1039.29,1255.82 1039.29,1333.44 1064.11,1358.27 1123.17,1358.27 1150.04,1385.14 1220.91,1385.14 1339.87,1504.1 1519.85,1504.1 1602.36,1586.61 1861.08,1586.61 1900.45,1547.24 2144.55,1547.24 2318.9,1372.89 2318.9,1181.18 2330.71,1169.37 2338.66,1169.37 v2(2342.52,1173.23)
HDMI_OUT_D0_N: J1.86 J6.9 U5.12 U5.27 | length 2323.4
  L1 w5.4: J1.86@1122.05,1159.06 1122.05,1175.79 1122.13,1175.87 1122.13,1224.49 1147.8,1250.16 1147.8,1281.33 1317.66,1451.19 1355.1,1451.19 1368.03,1438.26 1368.03,1414.67 1391.53,1391.17 1434.6,1391.17 1456.85,1413.42 1456.85,1437.01 1471.04,1451.19 1500.93,1451.19 1513.86,1438.26 1513.86,1414.67 1537.37,1391.17 1596.18,1391.17 1622.13,1417.11 1622.13,1468.58 v2(1625.98,1472.44) ; v2(2271.65,1165.35) 2275.51,1169.21 2293.99,1169.21 2337.3,1212.52 2345.1,1212.52 2356.83,1200.79 U5.12@2403.54,1200.79 2434.06,1200.79 2445.79,1212.52 2569.51,1212.52 2581.24,1200.79 U5.27@2627.95,1200.79 2658.47,1200.79 2670.2,1212.52 2679.35,1212.52 2691.08,1200.79 J6.9@2761.42,1200.79
  L6 w5.4: v2(1625.98,1472.44) 1622.13,1476.3 1622.13,1492.21 1637.8,1507.87 1826.77,1507.87 1866.14,1468.5 2087.74,1468.5 2216.54,1339.7 2216.54,1297.81 2209.38,1290.65 2202.49,1290.65 2194.62,1282.78 2194.62,1270.97 2202.49,1263.1 2209.35,1263.1 2216.54,1255.91 2216.54,1197.97 2245.3,1169.21 2267.8,1169.21 v2(2271.65,1165.35)
HDMI_OUT_D0_P: J1.88 J6.7 U5.10 U5.29 | length 2323.6
  L1 w5.4: J1.88@1106.3,1159.06 1106.3,1175.79 1106.22,1175.87 1106.22,1231.08 1131.89,1256.75 1131.89,1287.92 1268.28,1424.31 1311.07,1467.1 1361.69,1467.1 1383.94,1444.85 1383.94,1421.26 1398.12,1407.08 1428.01,1407.08 1440.94,1420.01 1440.94,1443.6 1464.45,1467.1 1507.52,1467.1 1529.77,1444.85 1529.77,1421.26 1543.96,1407.08 1589.59,1407.08 1606.22,1423.7 1606.22,1468.58 v2(1602.36,1472.44) ; v2(2271.65,1188.98) 2275.51,1185.12 2287.4,1185.12 2330.71,1228.43 2345.1,1228.43 2356.83,1240.16 U5.10@2403.54,1240.16 2434.06,1240.16 2445.79,1228.43 2569.51,1228.43 2581.24,1240.16 U5.29@2627.95,1240.16 2658.47,1240.16 2670.2,1228.43 2679.35,1228.43 2691.08,1240.16 J6.7@2761.42,1240.16
  L6 w5.4: v2(1602.36,1472.44) 1606.22,1476.3 1606.22,1498.8 1631.21,1523.78 1833.36,1523.78 1872.73,1484.41 2094.33,1484.41 2232.45,1346.29 2232.45,1204.56 2251.89,1185.12 2267.8,1185.12 v2(2271.65,1188.98)
HDMI_OUT_D1_N: J1.79 J6.6 U5.9 U5.30 | length 2322.5
  L1 w5.4: J1.79@1169.29,1037.8 1169.29,1054.53 1173.23,1058.47 v2(1173.23,1071.65) ; v2(2157.48,1236.22) 2161.34,1240.08 2191.71,1240.08 2212.6,1260.96 2212.6,1275.59 2236.22,1299.21 2257.03,1299.21 2284.67,1271.57 2361.3,1271.57 2373.03,1259.84 U5.9@2403.54,1259.84 2450.25,1259.84 2461.98,1271.57 2585.71,1271.57 2597.44,1259.84 U5.30@2627.95,1259.84 2674.66,1259.84 2686.39,1271.57 2695.55,1271.57 2707.28,1259.84 J6.6@2761.42,1259.84
  L6 w5.4: v2(1173.23,1071.65) 1169.37,1075.51 1169.37,1086.61 1189.14,1106.38 1189.14,1131.21 1207.54,1149.61 1266.88,1149.61 1286.73,1129.76 1313.68,1129.76 1340.55,1156.63 1340.55,1196 1362.37,1217.82 1362.37,1295.44 1421.26,1354.33 1484.25,1354.33 1491.4,1347.18 1491.4,1340.29 1499.28,1332.42 1511.09,1332.42 1518.96,1340.29 1518.96,1347.14 1526.15,1354.33 1559.05,1354.33 1590.71,1322.67 1628.64,1322.67 1660.3,1354.33 1795.28,1354.33 1807.09,1342.52 1807.09,1241.28 1829.34,1219.03 1872.41,1219.03 1895.91,1242.53 1895.91,1312.28 1908.85,1325.21 1938.73,1325.21 1952.92,1311.02 1952.92,1284.59 1975.17,1262.33 2018.24,1262.33 2041.74,1285.84 2041.74,1312.28 2055.93,1326.46 2085.82,1326.46 2102.2,1310.08 2102.2,1269 2131.12,1240.08 2153.62,1240.08 v2(2157.48,1236.22)
HDMI_OUT_D1_P: J1.81 J6.4 U5.7 U5.32 | length 2322.7
  L1 w5.4: v2(1149.61,1071.65) 1149.61,1058.47 1153.54,1054.53 J1.81@1153.54,1037.8 ; v2(2157.48,1259.84) 2161.34,1255.99 2185.12,1255.99 2196.69,1267.55 2196.69,1282.18 2229.63,1315.12 2263.62,1315.12 2291.26,1287.48 2361.3,1287.48 2373.03,1299.21 U5.7@2403.54,1299.21 2450.25,1299.21 2461.98,1287.48 2585.71,1287.48 2597.44,1299.21 U5.32@2627.95,1299.21 2674.66,1299.21 2686.39,1287.48 2695.55,1287.48 2707.28,1299.21 J6.4@2761.42,1299.21
  L6 w5.4: v2(1149.61,1071.65) 1153.46,1075.51 1153.46,1093.2 1173.23,1112.97 1173.23,1137.8 1200.95,1165.52 1273.47,1165.52 1293.32,1145.67 1307.09,1145.67 1324.64,1163.22 1324.64,1202.59 1346.46,1224.41 1346.46,1302.03 1414.67,1370.24 1565.65,1370.24 1597.3,1338.58 1622.05,1338.58 1653.71,1370.24 1801.87,1370.24 1823,1349.11 1823,1247.87 1835.93,1234.94 1865.82,1234.94 1880,1249.12 1880,1318.87 1902.25,1341.12 1945.32,1341.12 1968.83,1317.61 1968.83,1291.18 1981.76,1278.24 2011.65,1278.24 2025.83,1292.43 2025.83,1318.87 2049.34,1342.37 2092.41,1342.37 2118.11,1316.67 2118.11,1275.59 2137.71,1255.99 2153.62,1255.99 v2(2157.48,1259.84)
HDMI_OUT_D2_N: J1.85 J6.3 U5.6 U5.33 | length 2322.7
  L1 w5.4: J1.85@1122.05,1037.8 1122.05,1054.53 1125.98,1058.47 v2(1125.98,1071.65) ; v2(2098.43,1381.89) 2102.28,1385.75 2127.19,1385.75 2162.7,1350.23 2203.44,1350.23 2228.51,1375.3 2228.51,1416.04 2200.95,1443.6 2200.95,1471.16 2216.7,1486.91 2244.26,1486.91 2283.63,1447.54 2283.63,1358.11 2311.1,1330.63 2345.1,1330.63 2356.83,1318.9 U5.6@2403.54,1318.9 2434.06,1318.9 2445.79,1330.63 2569.51,1330.63 2581.24,1318.9 U5.33@2627.95,1318.9 2658.47,1318.9 2670.2,1330.63 2679.35,1330.63 2691.08,1318.9 J6.3@2761.42,1318.9
  L6 w5.4: v2(1125.98,1071.65) 1122.13,1075.51 1122.13,1106.38 1134.02,1118.27 1134.02,1148.32 1094.49,1187.85 1094.49,1216.54 1134.58,1256.63 1134.58,1272.38 1169.29,1307.09 1274.47,1307.09 1396.52,1429.13 1812.31,1429.13 1843.8,1397.64 1977.79,1397.64 1984.94,1390.49 1984.94,1383.6 1992.81,1375.72 2004.62,1375.72 2012.5,1383.6 2012.5,1390.45 2019.69,1397.64 2059.06,1397.64 2070.95,1385.75 2094.57,1385.75 v2(2098.43,1381.89)
HDMI_OUT_D2_P: J1.87 J6.1 U5.4 U5.35 | length 2322.9
  L1 w5.4: v2(1102.36,1071.65) 1102.36,1058.47 1106.3,1054.53 J1.87@1106.3,1037.8 ; v2(2098.43,1405.51) 2102.28,1401.66 2133.78,1401.66 2169.29,1366.14 2196.85,1366.14 2212.6,1381.89 2212.6,1409.45 2185.04,1437.01 2185.04,1477.75 2210.11,1502.82 2250.85,1502.82 2299.54,1454.13 2299.54,1364.7 2317.7,1346.54 2345.1,1346.54 2356.83,1358.27 U5.4@2403.54,1358.27 2434.06,1358.27 2445.79,1346.54 2569.51,1346.54 2581.24,1358.27 U5.35@2627.95,1358.27 2658.47,1358.27 2670.2,1346.54 2679.35,1346.54 2691.08,1358.27 J6.1@2761.42,1358.27
  L6 w5.4: v2(1102.36,1071.65) 1106.22,1075.51 1106.22,1112.97 1118.11,1124.86 1118.11,1141.73 1078.58,1181.26 1078.58,1223.13 1118.67,1263.22 1118.67,1278.97 1162.7,1323 1267.88,1323 1389.93,1445.04 1818.9,1445.04 1850.39,1413.55 2065.65,1413.55 2077.54,1401.66 2094.57,1401.66 v2(2098.43,1405.51)
HDMI_OUT_ESD_BYP: C24.1 U5.37 | length 128.5
  L1 w11.02: 2574.8,1409.45 2586.61,1397.64 U5.37@2627.95,1397.64
  L1 w15.75: C24.1@2547.24,1468.5 2547.24,1437.01 2574.8,1409.45
HDMI_OUT_HPD: J1.78 R41.2 U3.4 | length 1646
  L1 w5.4: J1.78@1185.04,1159.06 1185.04,1218.25 1201.24,1234.45 1289.57,1234.45 1307.09,1251.97 1342.52,1251.97 1366.14,1228.35 v2(1389.76,1228.35) ; R41.2@2322.83,1003.94 2322.83,1031.5 v2(2326.77,1035.43)
  L6 w5.4: v2(1389.76,1228.35) 1389.76,1210.37 1379.72,1200.33 1379.72,1167.52 1401.57,1145.67 1401.57,1118.11 1426.08,1093.6 1426.08,1080.87 1469.55,1037.4 1519.69,1037.4 1563.19,993.9 1753.74,993.9 1771.65,1011.81 1811.02,1011.81 1909.45,1110.24 1909.45,1122.05 1980.32,1192.91 2102.36,1192.91 2177.17,1118.11 2240.16,1118.11 v2@2322.83,1035.43 ; U3.4@2360.24,1080.71 2360.24,1068.9 v2(2326.77,1035.43) ; v2@2322.83,1035.43 v2(2326.77,1035.43) ; v2@2322.83,1035.43 v2(2326.77,1035.43)
HDMI_OUT_HPD_CON: C108.1 J6.19 R47.2 U5.20 | length 263.2
  L1 w5.4: U5.20@2627.95,1062.99 2594.49,1062.99 2586.61,1055.12 2586.61,1019.68 2598.43,1007.87 R47.2@2610.24,1007.87 2673.23,1007.87 2679.33,1001.77 2696.85,1001.77 2699.02,1003.94 J6.19@2761.42,1003.94
HDMI_OUT_HPD_R: R36.1 R41.1 U3.2 U5.19 | length 214.1
  L1 w5.4: v2@2362.2,976.38 R41.1@2362.2,1003.94 R36.1@2409.45,1003.94 2437.01,1031.5 2437.01,1047.24 2421.26,1062.99 U5.19@2403.54,1062.99
  L6 w5.4: v2(2366.14,976.38) 2374.02,976.38 2377.95,976.38 2385.83,984.25 2385.83,988.19 U3.2@2385.83,1005.91
HDMI_OUT_SCL_CON: J6.15 R15.1 | length 105.6
  L1 w5.4: v2(2688.98,1082.68) J6.15@2761.42,1082.68
  L6 w5.4: v2(2688.98,1082.68) 2692.91,1078.74 R15.1@2720.47,1078.74
HDMI_OUT_SCL_CON_R: R15.2 R19.1 U5.22 | length 213.2
  L1 w5.4: v2(2570.87,1102.36) U5.22@2627.95,1102.36
  L6 w5.4: v2(2570.87,1102.36) 2586.61,1118.11 R19.1@2653.54,1118.11 R15.2@2720.47,1118.11
HDMI_OUT_SDA_CON: J6.16 R16.1 | length 117
  L1 w5.4: v2(2688.98,1051.18) 2700.79,1062.99 J6.16@2761.42,1062.99
  L6 w5.4: v2(2688.98,1051.18) 2700.79,1051.18 R16.1@2720.47,1031.5
HDMI_OUT_SDA_CON_R: R16.2 R17.1 U5.21 | length 270.1
  L1 w5.4: v2(2559.06,1055.12) 2559.06,1059.06 2582.68,1082.68 U5.21@2627.95,1082.68
  L6 w5.4: v2(2559.06,1055.12) 2622.05,992.13 R16.2@2720.47,992.13
I2C1_SCL: J2.26 J19.1 U5.17 | length 5434.4
  L1 w5.4: v1(795.28,2196.85) 767.72,2169.29 767.72,2122.05 700.79,2055.12 700.79,2003.94 744.09,1960.63 744.09,1921.26 771.05,1894.3 771.05,1846.46 786.8,1830.71 J2.26@801.57,1830.71 ; v1(1326.77,2858.27) 1358.27,2889.76 1358.27,2972.44 1389.76,3003.94 1389.76,3350.39 1496.06,3456.69 1610.24,3456.69 1665.35,3401.57 1665.35,3338.58 1614.17,3287.4 J19.1@1614.17,3267.72 1614.17,3228.35 1645.67,3196.85 1846.46,3196.85 1874.02,3169.29 2002.23,3169.29 2204.72,2966.79 2204.72,2818.9 2348.23,2675.39 2348.23,1777.36 2279.53,1708.66 2279.53,1669.29 2051.18,1440.94 2051.18,1291.34 2250.2,1092.32 2349.94,1092.32 2359.98,1102.36 U5.17@2403.54,1102.36
  L3 w5.9: v1(795.28,2196.85) 1169.29,2570.87 1169.29,2602.36 1204.72,2637.8 1255.91,2637.8 1275.59,2657.48 1275.59,2708.66 1346.46,2779.53 1346.46,2838.58 v1(1326.77,2858.27)
I2C1_SDA: J2.28 J19.2 U5.18 | length 5365.1
  L1 w5.4: v1(795.28,2236.22) 740.16,2181.1 740.16,2129.92 681.1,2070.87 681.1,1992.13 724.41,1948.82 724.41,1913.39 751.97,1885.83 751.97,1846.46 783.46,1814.96 J2.28@801.57,1814.96 ; v1(1326.77,2822.83) 1385.83,2881.89 1385.83,2952.76 1417.32,2984.25 1417.32,3314.96 1521.36,3419 1596.75,3419 1614.17,3401.57 J19.2@1614.17,3367.72 1559.06,3312.6 1559.06,3236.22 1625.98,3169.29 1830.71,3169.29 1854.33,3145.67 1996.06,3145.67 2173.23,2968.5 2173.23,2811.02 2326.77,2657.48 2326.77,2515.75 2299.21,2488.19 2299.21,1889.76 2251.97,1842.52 2251.97,1671.52 2027.56,1447.11 2027.56,1287.4 2244.09,1070.87 2356.89,1070.87 2368.7,1082.68 U5.18@2403.54,1082.68
  L3 w5.9: v1(795.28,2236.22) 1125.98,2566.93 1125.98,2622.05 v1(1326.77,2822.83)
I2C2_CSI_SCL: J12.13 R135.1 | length 1137.5
  L1 w5.4: v1(200.79,1220.47) J12.13@251.97,1220.47
  L6 w5.4: v1(200.79,1220.47) 182.87,1202.56 182.87,1173.68 236.22,1120.34 236.22,1070.87 271.65,1035.43 350.39,1035.43 377.95,1007.87 448.82,1007.87 566.93,889.76 566.93,700.79 724.41,543.31 773.88,543.31 795.28,564.7 R135.1@795.28,574.8
I2C2_CSI_SDA: J12.14 R136.1 | length 966.7
  L1 w5.4: v1(200.79,1181.1) J12.14@251.97,1181.1
  L6 w5.4: v1(200.79,1181.1) 255.91,1125.98 255.91,1078.74 279.53,1055.12 366.14,1055.12 394.88,1026.38 456.16,1026.38 594.49,888.05 594.49,708.66 647.44,655.71 735.77,655.71 755.91,635.57 R136.1@755.91,633.86
I2C2_DDC_SCL: R6.1 R9.2 U1.A3 U4.17 | length 840.4
  L1 w5.4: U4.17@891.73,755.91 854.33,755.91 846.46,763.78 846.46,803.15 870.08,826.77 885.83,826.77 925.2,866.14 925.2,913.39 933.07,921.26 968.5,921.26 976.38,913.39 R9.2@988.19,901.57 ; R9.2@988.19,893.7 R9.2@988.19,901.57 ; U1.A3@1289.37,639.76 1289.37,649.61 1289.17,649.8 1289.17,663.58 1279.53,673.23 1279.53,685.04 1241.14,723.43 1193.9,723.43 1161.42,755.91 1161.42,877.95 1145.67,893.7 R6.1@1129.92,893.7 1102.36,921.26 1007.87,921.26 R9.2@988.19,901.57
I2C2_DDC_SDA: R7.1 R8.2 U1.B3 U4.18 | length 540.7
  L1 w3.94: 1279.53,645.67 1279.53,629.92 U1.B3@1289.37,620.08
  L1 w5.4: U4.18@891.73,775.59 944.88,775.59 968.5,799.21 997.83,799.21 1013.58,814.96 ; R8.2@1015.75,826.77 1013.58,824.61 1013.58,814.96 ; 1279.53,645.67 1279.53,653.54 1250.2,682.87 1227.49,682.87 1199.14,711.22 1182.48,711.22 1129.92,763.78 R7.1@1129.92,767.72 1090.55,767.72 1082.68,775.59 1023.62,775.59 1013.58,785.63 1013.58,814.96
